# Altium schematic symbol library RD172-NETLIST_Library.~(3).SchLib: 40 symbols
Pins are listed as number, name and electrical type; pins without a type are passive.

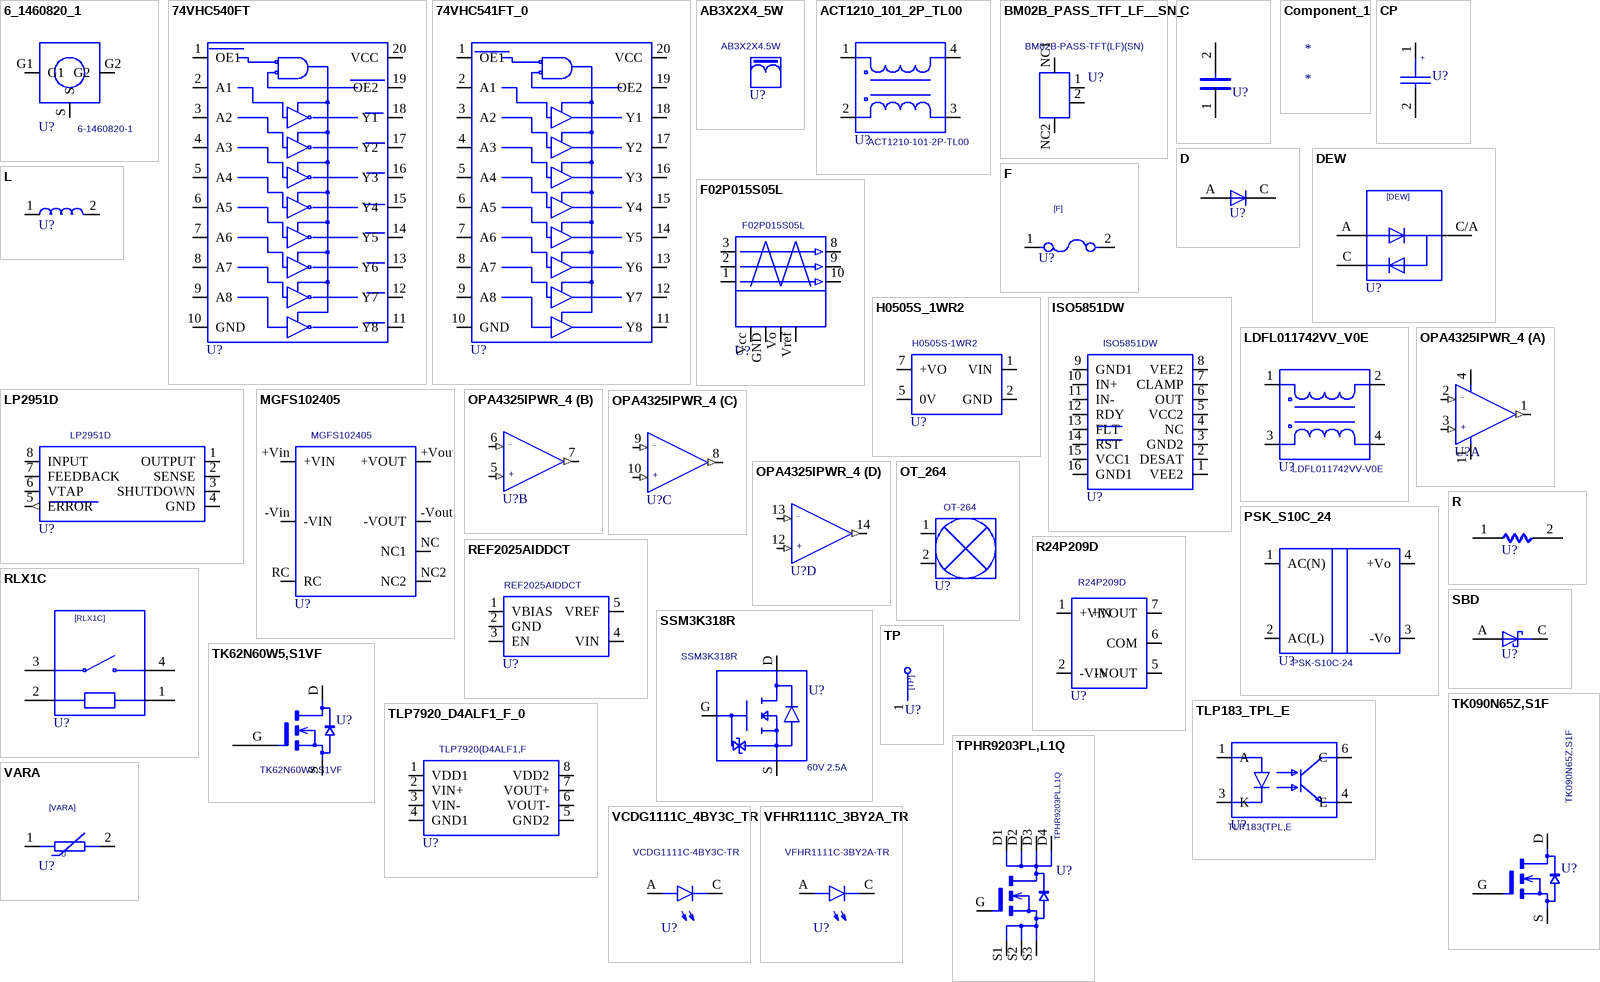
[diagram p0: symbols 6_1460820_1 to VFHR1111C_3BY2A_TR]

## 6_1460820_1
designator U?, comment 6-1460820-1
MMCX Connector, 170V; MANUFACTURER: TE Connectivity; TIME: 16:53:54; UPDATEUSER: t5459927; UPDATETIME: 16:17:04; SAVECOUNT: 3; SAVEAREA0: -4427,-12981,14210,683; OriginalSymbolOrigin: (0,0); Altium-Right: 40
pins: G1, G2, S

## 74VHC540FT
designator U?  (value not drawn)
Buffer; MANUFACTURER: TOSHIBA; TIME: 16:53:55; UPDATEUSER: t5459927; UPDATETIME: 14:02:13; SAVECOUNT: 3; SAVEAREA0: -17145,-25086,46711,10262; OriginalSymbolOrigin: (0,0); Altium-Right: 120; Altium-Bottom: 200
pins: 1 OE1, 2 A1, 3 A2, 4 A3, 5 A4, 6 A5, 7 A6, 8 A7, 9 A8, 10 GND, 11 Y8, 12 Y7, 13 Y6, 14 Y5, 15 Y4, 16 Y3, 17 Y2, 18 Y1, 19 OE2, 20 VCC

## 74VHC541FT_0
designator U?, comment 74VHC541FT  (value not drawn)
Buffer; MANUFACTURER: TOSHIBA; COMP: 74VHC541FT_0; TIME: 16:53:58; UPDATEUSER: t5459927; UPDATETIME: 13:53:55; SAVECOUNT: 7; SAVEAREA0: -71383,-60147,106563,38358; OriginalSymbolOrigin: (0,0); Altium-Right: 120; Altium-Bottom: 200
pins: 1 OE1, 2 A1, 3 A2, 4 A3, 5 A4, 6 A5, 7 A6, 8 A7, 9 A8, 10 GND, 11 Y8, 12 Y7, 13 Y6, 14 Y5, 15 Y4, 16 Y3, 17 Y2, 18 Y1, 19 OE2, 20 VCC

## AB3X2X4_5W
designator U?, comment AB3X2X4.5W
AMOBEADS; MANUFACTURER: Toshiba; NOTE: 5uH; TIME: 16:53:53; UPDATEUSER: t5459927; UPDATETIME: 16:18:50; SAVECOUNT: 3; SAVEAREA0: -1267,-5201,6185,262; OriginalSymbolOrigin: (0,0); Altium-Right: 20

## ACT1210_101_2P_TL00
designator U?, comment ACT1210-101-2P-TL00
150mA; MAKER: TDK; NOTE: 100uH; TIME: 16:53:54; UPDATEUSER: t5459927; UPDATETIME: 16:07:31; SAVECOUNT: 2; SAVEAREA0: -3836,-15544,18528,852; OriginalSymbolOrigin: (0,0); Altium-Right: 60
pins: 1, 2, 3, 4

## BM02B_PASS_TFT_LF__SN_
designator U?, comment BM02B-PASS-TFT(LF)(SN)
Connector, 250V, 3A; MANUFACTURER: JST; NOTE: 2pin; TIME: 16:53:54; UPDATEUSER: t5459927; UPDATETIME: 16:10:14; SAVECOUNT: 2; SAVEAREA0: -5711,-10440,12927,3224; OriginalSymbolOrigin: (0,0); Altium-Right: 20; Altium-Bottom: 30
pins: 1, 2, NC1 PAD1, NC2 PAD2

## C
designator U?  (value not drawn)
OriginalSymbolOrigin: (2540,7620); Altium-Right: 20; Altium-Bottom: 10
pins: 1, 2

## Component_1
designator *

## CP
designator U?  (value not drawn)
SAVEAREA0: -1450,-153,20294,13055; SAVECOUNT: 52; TIME: 15:02:55; UPDATEUSER: fukuda-y; UPDATETIME: 16:13:42; OriginalSymbolOrigin: (2540,10160); Altium-Right: 20
pins: 1 2, 2 1

## D
designator U?  (value not drawn)
SAVEAREA0: -225,-91,12804,7836; SAVECOUNT: 3; TIME: 14:49:55; UPDATEUSER: 19870035; UPDATETIME: 14:20:16; OriginalSymbolOrigin: (5080,5080); Altium-Right: 10; Altium-Bottom: 20
pins: A, C

## DEW
designator U?  (value not drawn)
SAVEAREA0: -10024,-234,32508,20938; TIME: 14:49:55; UPDATEUSER: 19990028; UPDATETIME: 14:00:58; SAVECOUNT: 4; OriginalSymbolOrigin: (5080,17780); Altium-Right: 50; Altium-Bottom: 60
pins: A, C, C/A AC

## F
designator U?  (value not drawn)
OriginalSymbolOrigin: (2540,5080); Altium-Right: 40; Altium-Bottom: 20
pins: 1, 2

## F02P015S05L
designator U?
Current Transducer, 15A; MANUFACTURER: Tamura; TIME: 16:53:55; UPDATEUSER: t5459927; UPDATETIME: 16:08:01; SAVECOUNT: 2; SAVEAREA0: -5739,-18135,20354,994; OriginalSymbolOrigin: (0,0); Altium-Right: 60
pins: 1, 2, 3, 8, 9, 10, GND, Vcc VCC, Vo, Vref

## H0505S_1WR2
designator U?, comment H0505S-1WR2
DC/DC Converter; MANUFACTURER: MORNSUN; TIME: 16:53:55; UPDATEUSER: t5459927; UPDATETIME: 14:51:35; SAVECOUNT: 2; SAVEAREA0: -3365,-12675,18085,3050; OriginalSymbolOrigin: (0,0); Altium-Right: 60; Altium-Bottom: 40
pins: 1 VIN, 2 GND, 5 0V, 7 +VO

## ISO5851DW
designator U?
Gate Driver; MANUFACTURER: Txsas Instruments; TIME: 16:53:55; UPDATEUSER: t5459927; UPDATETIME: 16:13:36; SAVECOUNT: 2; SAVEAREA0: -16530,-29444,33798,7453; OriginalSymbolOrigin: (0,0); Altium-Right: 70; Altium-Bottom: 90
pins: 1 VEE2, 2 DESAT, 3 GND2, 4 NC, 5 VCC2, 6 OUT, 7 CLAMP, 8 VEE2, 9 GND1, 10 IN+, 11 IN-, 12 RDY, 13 FLT, 14 RST, 15 VCC1, 16 GND1

## L
designator U?  (value not drawn)
OriginalSymbolOrigin: (2540,5080); Altium-Right: 30; Altium-Bottom: 20
pins: 1, 2

## LDFL011742VV_V0E
designator U?, comment LDFL011742VV-V0E
11A; MANUFACTURER: Nippon Chemi-Con; NOTE: 7.4mH; TIME: 16:53:58; UPDATEUSER: t5459927; UPDATETIME: 14:44:17; SAVECOUNT: 2; SAVEAREA0: -3836,-15544,18528,852; OriginalSymbolOrigin: (0,0); Altium-Right: 60
pins: 1, 2, 3, 4

## LP2951D
designator U?
Voltage Regulators; MANUFACTURER: Txsas Instruments; TIME: 16:53:55; UPDATEUSER: t5459927; UPDATETIME: 16:15:29; SAVECOUNT: 3; SAVEAREA0: -15946,-25147,36340,13186; OriginalSymbolOrigin: (0,0); Altium-Right: 110; Altium-Bottom: 50
pins: 1 OUTPUT, 2 SENSE, 3 SHUTDOWN, 4 GND, 5 ERROR (out), 6 VTAP, 7 FEEDBACK, 8 INPUT

## MGFS102405
designator U?
DC/DC Converter; MANUFACTURER: COSEL; TIME: 16:53:55; UPDATEUSER: t5459927; UPDATETIME: 16:09:02; SAVECOUNT: 2; SAVEAREA0: -8909,-25908,28368,1421; OriginalSymbolOrigin: (0,0); Altium-Right: 80; Altium-Bottom: 100
pins: +Vin +VIN, +Vout +VOUT, -Vin -VIN, -Vout -VOUT, NC NC1, NC2, RC

## OPA4325IPWR_4
designator U?  (value not drawn)
TIME: 16:31:59; UPDATEUSER: t5459927; UPDATETIME: 16:35:50; SAVECOUNT: 11; SAVEAREA0: -17633,-13280,32685,23610; OriginalSymbolOrigin: (2540,10160); Altium-Right: 40
part A pins: 1 OUT (out), 2 IN- (in), 3 IN+ (in), 4 V+, 11 V-
part B pins: 5 (in), 6 (in), 7 (out)
part C pins: 8 (out), 9 (in), 10 (in)
part D pins: 12 (in), 13 (in), 14 (out)

## OT_264
designator U?, comment OT-264
Terminal, 50A, M4; MANUFACTURER: Osada; TIME: 16:53:54; UPDATEUSER: t5459927; UPDATETIME: 16:17:50; SAVECOUNT: 2; SAVEAREA0: -3825,-10384,11084,546; OriginalSymbolOrigin: (0,0); Altium-Right: 40
pins: 1, 2

## PSK_S10C_24
designator U?, comment PSK-S10C-24
AC/DC Converter; MANUFACTURER: CUI INC; TIME: 16:53:55; UPDATEUSER: t5459927; UPDATETIME: 14:43:43; SAVECOUNT: 2; SAVEAREA0: -3577,-18400,23236,1258; OriginalSymbolOrigin: (0,0); Altium-Right: 80; Altium-Bottom: 70
pins: 1 AC(N), 2 AC(L), 3 -Vo, 4 +Vo

## R
designator U?  (value not drawn)
OriginalSymbolOrigin: (5080,5080); Altium-Right: 20
pins: 1, 2

## R24P209D
designator U?
DC/DC Converter; MANUFACTURER: RECOM; TIME: 16:53:55; UPDATEUSER: t5459927; UPDATETIME: 16:11:38; SAVECOUNT: 2; SAVEAREA0: -5083,-15544,17282,852; OriginalSymbolOrigin: (0,0); Altium-Right: 50; Altium-Bottom: 60
pins: 1 +VIN, 2 -VIN, 5 -VOUT, 6 COM, 7 +VOUT

## REF2025AIDDCT
designator U?
Voltage References; MANUFACTURER: Texas Instruments; TIME: 16:53:54; UPDATEUSER: t5459927; UPDATETIME: 13:28:15; SAVECOUNT: 3; SAVEAREA0: -3432,-13658,20699,4033; OriginalSymbolOrigin: (0,0); Altium-Right: 70; Altium-Bottom: 40
pins: 1 VBIAS, 2 GND, 3 EN, 4 VIN, 5 VREF

## RLX1C
designator U?  (value not drawn)
SAVECOUNT: 9; SAVEAREA0: -9347,-440,34039,23986; OriginalSymbolOrigin: (5080,20320); Altium-Right: 60; Altium-Bottom: 70
pins: 1, 2, 3, 4

## SBD
designator U?  (value not drawn)
SAVEAREA0: -4630,-153,17114,13055; TIME: 14:49:55; UPDATEUSER: fukuda-y; UPDATETIME: 08:16:22; SAVECOUNT: 9; OriginalSymbolOrigin: (5080,5080); Altium-Right: 20
pins: A, C

## SSM3K318R
designator U?  NOTE: 60V 2.5A
MOSFET; MANUFACTURER: TOSHIBA; TIME: 16:53:56; UPDATEUSER: t5459927; UPDATETIME: 14:46:06; SAVECOUNT: 2; SAVEAREA0: -8920,-18190,20901,3672; OriginalSymbolOrigin: (0,0); Altium-Right: 60
pins: D, G, S

## TK62N60W5,S1VF
designator U?
Nch MOSFET; MAKER: Toshiba; NOTE: 600V 61.8A; TIME: 16:53:55; UPDATEUSER: t5459927; SAVECOUNT: 1; OriginalSymbolOrigin: (0,0); Altium-Right: 40
pins: D, G, S

## TK090N65Z,S1F
designator U?
Power MOS FET; MANUFACTURER: TOSHIBA; NOTE: 650V 30A; TIME: 16:53:56; UPDATEUSER: t5459927; SAVECOUNT: 1; OriginalSymbolOrigin: (0,0); Altium-Right: 40
pins: D, G, S

## TLP183_TPL_E
designator U?, comment TLP183(TPL,E
Photocoupler; MANUFACTURER: TOSHIBA; TIME: 16:53:54; UPDATEUSER: t5459927; UPDATETIME: 16:20:20; SAVECOUNT: 2; SAVEAREA0: -3467,-14897,20665,2795; OriginalSymbolOrigin: (0,0); Altium-Right: 70; Altium-Bottom: 50
pins: 1 A, 3 K, 4 E, 6 C

## TLP7920_D4ALF1_F_0
designator U?, comment TLP7920(D4ALF1,F
Photocoupler; MANUFACTURER: TOSHIBA; COMP: TLP7920(D4ALF1,F_0; TIME: 16:53:58; UPDATEUSER: t5459927; UPDATETIME: 16:21:24; SAVECOUNT: 2; SAVEAREA0: -6097,-17212,23397,4411; OriginalSymbolOrigin: (0,0); Altium-Right: 90; Altium-Bottom: 50
pins: 1 VDD1, 2 VIN+, 3 VIN-, 4 GND1, 5 GND2, 6 VOUT-, 7 VOUT+, 8 VDD2

## TP
designator U?  (value not drawn)
TIME: 16:12:21; UPDATEUSER: fukuda-y; UPDATETIME: 16:18:11; SAVECOUNT: 2; SAVEAREA0: -242,-92,12810,7836; OriginalSymbolOrigin: (0,7620); Altium-Right: 20; Altium-Bottom: 30
pins: 1

## TPHR9203PL,L1Q
designator U?
Power MOS FET; MANUFACTURER: TOSHIBA; NOTE: 30V, 150A; TIME: 16:53:55; UPDATEUSER: t5459927; SAVECOUNT: 1; OriginalSymbolOrigin: (0,0); Altium-Right: 50; Altium-Bottom: 60
pins: D1, D2, D3, D4, G, S1, S2, S3

## VARA
designator U?  (value not drawn)
SAVEAREA0: -9950,-8554,25168,13619; SAVECOUNT: 12; TIME: 09:56:50; UPDATEUSER: tomizawa-y; OriginalSymbolOrigin: (2540,5080); Altium-Right: 40; Altium-Bottom: 20
pins: 1, 2

## VCDG1111C_4BY3C_TR
designator U?, comment VCDG1111C-4BY3C-TR
LED; MANUFACTURER: STANLEY; NOTE: Green; TIME: 16:53:54; UPDATEUSER: t5459927; SAVECOUNT: 1; OriginalSymbolOrigin: (0,-2540); Altium-Right: 30
pins: A, C

## VFHR1111C_3BY2A_TR
designator U?, comment VFHR1111C-3BY2A-TR
LED; MANUFACTURER: STANLEY; NOTE: Red; TIME: 16:53:54; UPDATEUSER: t5459927; SAVECOUNT: 1; OriginalSymbolOrigin: (0,-2540); Altium-Right: 30
pins: A, C

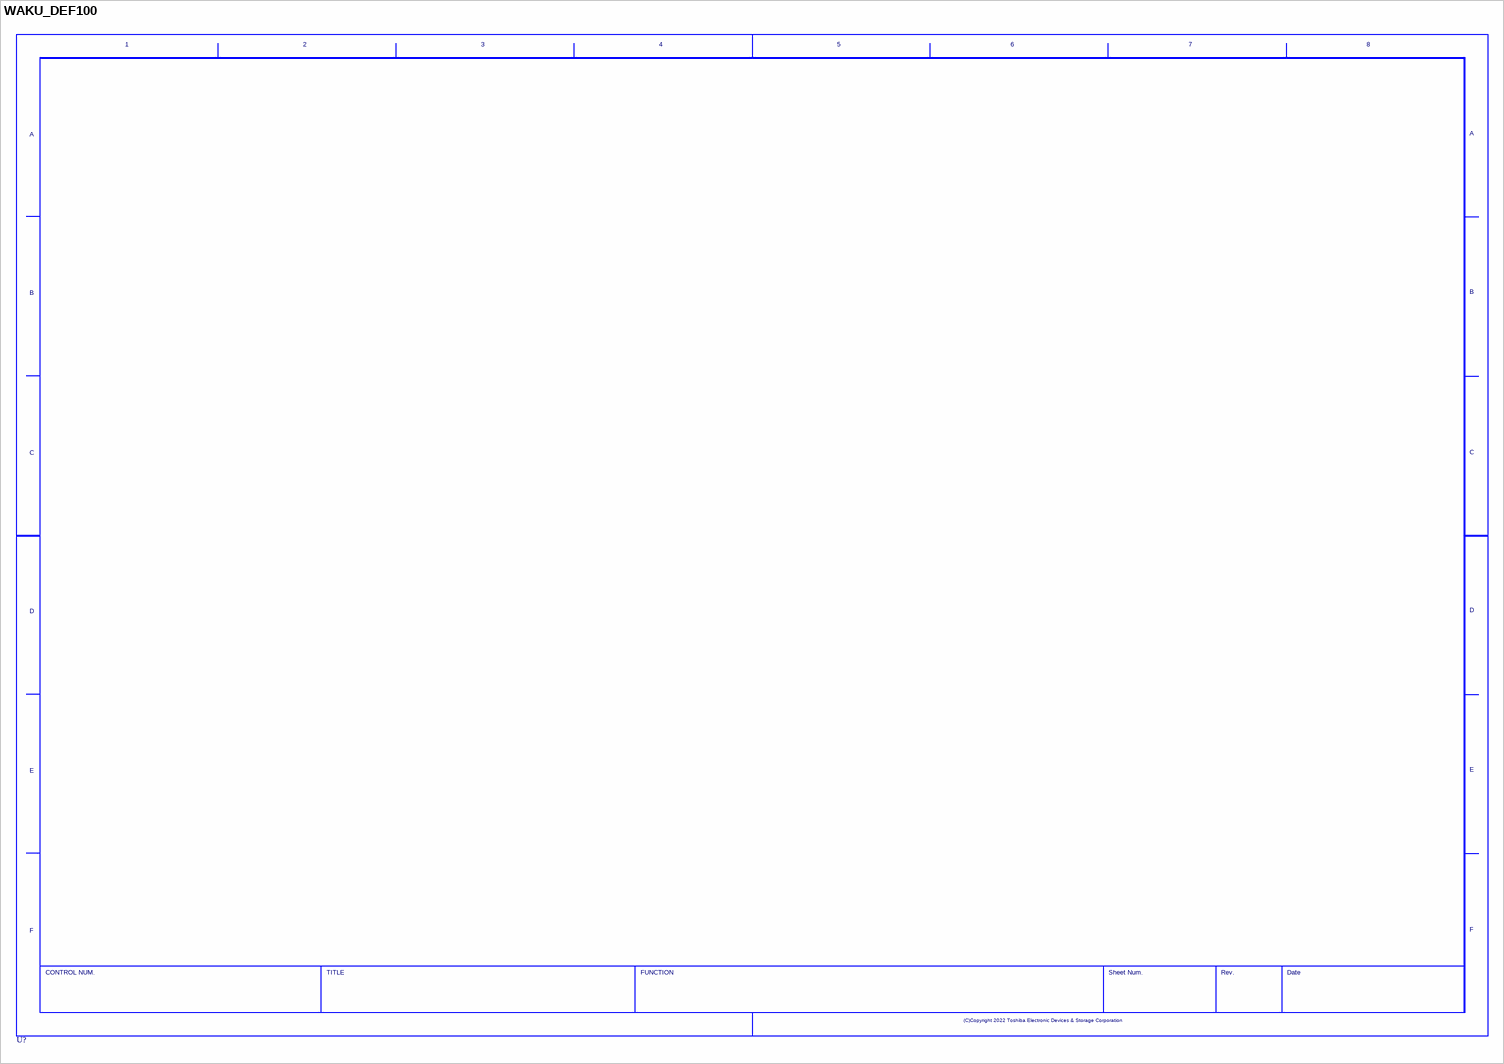
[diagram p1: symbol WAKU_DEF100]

## WAKU_DEF100
designator U?  (value not drawn)
PLOTTIME: HH:MM; SAVEAREA0: 22200,72372,612276,319236; TIME: 14:30:25; UPDATEUSER: t5459927; UPDATETIME: 17:12:32; SAVECOUNT: 7; OriginalSymbolOrigin: (10160,284480); Altium-Right: 1570; Altium-Bottom: 1070

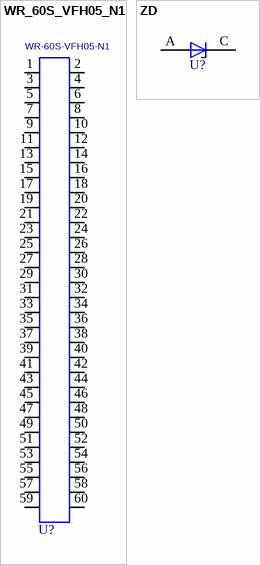
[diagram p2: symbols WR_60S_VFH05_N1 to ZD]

## WR_60S_VFH05_N1
designator U?, comment WR-60S-VFH05-N1
Terminal, 200V, 0.3A; MANUFACTURER: JAE; NOTE: 60pin; TIME: 16:53:54; UPDATEUSER: t5459927; UPDATETIME: 14:46:38; SAVECOUNT: 2; SAVEAREA0: -56595,-80318,58967,4405; OriginalSymbolOrigin: (0,0); Altium-Right: 20; Altium-Bottom: 310
pins: 1, 2, 3, 4, 5, 6, 7, 8, 9, 10, 11, 12, 13, 14, 15, 16, 17, 18, 19, 20, 21, 22, 23, 24, 25, 26, 27, 28, 29, 30, 31, 32, 33, 34, 35, 36, 37, 38, 39, 40, 41, 42, 43, 44, 45, 46, 47, 48, 49, 50, 51, 52, 53, 54, 55, 56, 57, 58, 59, 60

## ZD
designator U?  (value not drawn)
SAVEAREA0: -4630,-153,17114,13055; TIME: 14:49:55; UPDATEUSER: fukuda-y; UPDATETIME: 08:18:42; SAVECOUNT: 6; OriginalSymbolOrigin: (5080,5080); Altium-Right: 10; Altium-Bottom: 20
pins: A, C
